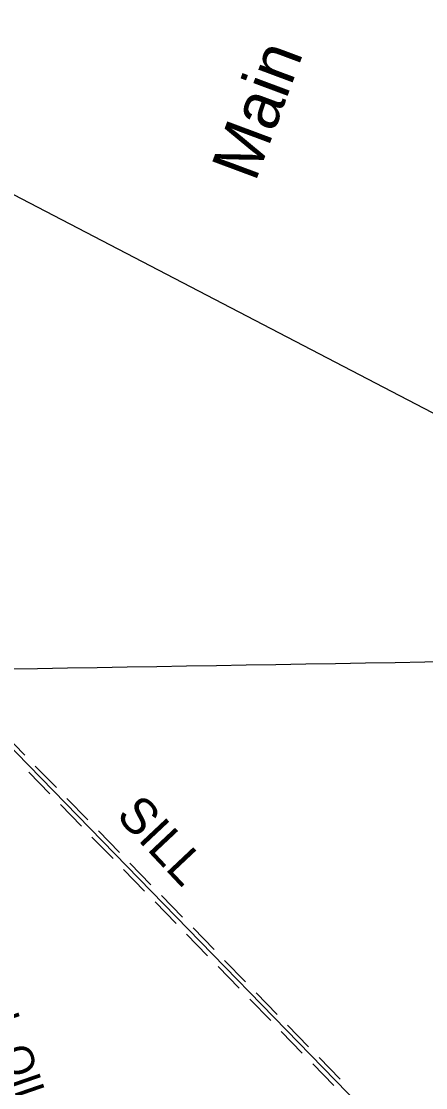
# Model space of a CAD drawing. Extents: x 3914892 to 3953151, y 242587 to 268572.
# Drawn here: x 3941826 to 3942954, y 259377 to 262347 of the extents above; entities that cross this region are included whole.
import ezdxf

# ---------------------------------------------------------------- set-up
doc = ezdxf.new("R2010")
doc.units = 0
for name, color, linetype in [('V-GRID-MAJR', 7, 'Continuous'), ('V-RIVR-EDGE', 7, 'Continuous'), ('V-RIVR-IDEN', 7, 'Continuous'), ('V-RRAP-DIKE', 7, 'Continuous'), ('V-RRAP-SILL-IDEN', 7, 'Continuous'), ('V-UTIL-IDEN', 7, 'Continuous')]:
    doc.layers.add(name, color=color, linetype=linetype)

msp = doc.modelspace()

# ---------------------------------------------------------------- linework, layer by layer
at = {"layer": 'V-GRID-MAJR'}
msp.add_spline([(3918942.3880000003, 260140.297), (3924259.416, 260233.496), (3929576.431, 260327.467), (3934893.433, 260422.212), (3940210.42, 260517.73), (3945527.394, 260614.022), (3950844.353, 260711.087), (3950844.3540000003, 260711.087)], degree=3, dxfattribs=at)
at = {"layer": 'V-RIVR-EDGE'}
msp.add_lwpolyline([(3941436.263321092, 261915.74149882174), (3941436.4269929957, 261918.19657738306), (3941474.2483207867, 261918.19657738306), (3941500.432316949, 261947.2899064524), (3941526.6163131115, 261947.2899064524), (3941578.9843054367, 261982.20190133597), (3943106.3840815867, 261187.95401773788)], dxfattribs=at)
at = {"layer": 'V-RRAP-DIKE'}
for points in [[(3942941.2560776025, 259151.36467211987), (3940956.965046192, 261187.10560062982)], [(3941836.201287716, 260302.97536889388), (3941777.56940498, 260363.12724859)], [(3941906.247147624, 260195.29758425), (3941847.615264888, 260255.44946394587)], [(3941924.1491118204, 260212.7475493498), (3941865.517229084, 260272.8994290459)], [(3941994.1949717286, 260105.0697647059), (3941935.563088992, 260165.22164440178)], [(3942012.096935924, 260122.51972980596), (3941953.4650531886, 260182.67160950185)], [(3942082.1427958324, 260014.84194516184), (3942023.5109130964, 260074.99382485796)], [(3942100.044760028, 260032.29191026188), (3942041.4128772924, 260092.443789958)], [(3942170.090619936, 259924.61412561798), (3942111.4587371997, 259984.76600531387)], [(3942187.992584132, 259942.0640907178), (3942129.360701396, 260002.21597041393)], [(3942258.0384440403, 259834.3863060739), (3942199.4065613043, 259894.5381857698)], [(3942275.940408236, 259851.83627117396), (3942217.3085255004, 259911.98815086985)], [(3942345.986268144, 259744.15848652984), (3942287.3543854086, 259804.31036622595)], [(3942363.88823234, 259761.60845162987), (3942305.256349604, 259821.76033132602)], [(3942433.934092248, 259653.93066698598), (3942375.302209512, 259714.0825466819)], [(3942451.8360564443, 259671.3806320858), (3942393.204173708, 259731.53251178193)], [(3942521.8819163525, 259563.70284744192), (3942463.250033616, 259623.8547271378)], [(3942539.783880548, 259581.15281254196), (3942481.1519978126, 259641.30469223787)], [(3942627.731704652, 259490.9249929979), (3942569.0998219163, 259551.07687269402)], [(3942609.8297404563, 259473.47502789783), (3942551.1978577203, 259533.62690759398)], [(3942715.679528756, 259400.6971734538), (3942657.04764602, 259460.84905314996)], [(3942697.77756456, 259383.247208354), (3942639.145681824, 259443.3990880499)]]:
    msp.add_lwpolyline(points, dxfattribs=at)

# ---------------------------------------------------------------- texts
at = {"layer": 'V-RIVR-IDEN'}
msp.add_text('Main     Pass', height=132.99973599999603, rotation=69.58222940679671, dxfattribs=at).set_placement((3942478.767002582, 261896.87618108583))
at = {"layer": 'V-RRAP-SILL-IDEN'}
msp.add_text('SILL', height=99.999801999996, rotation=313.2138683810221, dxfattribs=at).set_placement((3942087.995784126, 260132.47470989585))
at = {"layer": 'V-UTIL-IDEN'}
msp.add_text('SHELL OIL CO.', height=82.99983200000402, rotation=289.0439256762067, dxfattribs=at).set_placement((3941642.5110820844, 259841.68528137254))

doc.saveas('drawing.dxf')
